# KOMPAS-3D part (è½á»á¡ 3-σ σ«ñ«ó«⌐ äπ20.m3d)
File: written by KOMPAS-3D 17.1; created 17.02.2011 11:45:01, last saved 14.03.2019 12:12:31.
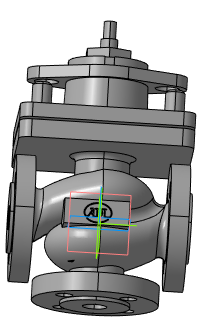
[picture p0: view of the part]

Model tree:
1. Плоскость XY
2. Плоскость ZX
3. Плоскость ZY
4. Ось X
5. Ось Y
6. Ось Z
7. Начало координат
8. Операция без истории:2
